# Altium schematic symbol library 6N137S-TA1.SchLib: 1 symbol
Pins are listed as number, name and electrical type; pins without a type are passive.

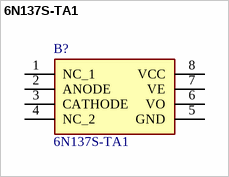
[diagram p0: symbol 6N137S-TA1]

## 6N137S-TA1
designator B?
High Speed Optocouplers High Speed 10MBd LogicGate Output; Manufacturer_Name: Lite-On; Geometry.Height: 4.6mm
footprint SOP254P1016X460-8N
pins: 1 NC_1, 2 ANODE, 3 CATHODE, 4 NC_2, 5 GND, 6 VO, 7 VE, 8 VCC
